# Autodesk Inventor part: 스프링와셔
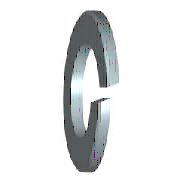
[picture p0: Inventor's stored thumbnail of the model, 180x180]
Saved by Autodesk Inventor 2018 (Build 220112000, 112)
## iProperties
Created: 2012-02
Part Number: 스프링와셔
Material: 강철, 연강
Description: 스프링 와셔
Document SubType Name: Modeling
Standard: JIS B 1251
Designer: mduedu
Standards Organization: JIS
Language: ko-KR
Size Designation: 번호 2 4
Categories: <MemberInstance><Categories><Category DisplayName="조임쇠" InternalName="e4da775c-781d-43d5-af7c-5136215cf5a6" Mnemonic="FSTN"><Category DisplayName="와셔" InternalN
Density: 7.85 g/cm^3
Appearance: 파란색 - 벽 페인트 - 광택
Mass: 0.246957 g
Surface Area: 1.02615 cm^2
Volume: 0.0314594 cm^3
IsCustomPart: 1
Author: mduedu
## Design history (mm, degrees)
sketch "스케치1"
  geometry: C1 r 3.8 at (0, 0); C2 r 2.05 at (0, 0); 1 further point
  constraints: 2 centre point, 2 coincident
  dimensions: "d0" = 4.1 diameter of C2 (= SD1); "d1" = 7.6 diameter of C1 (= SD2)
extrude "본체" new body sketch "스케치1" distance "d2" = 1 (= SD); taper "d3" = 0 deg
sketch "스케치2"
  geometry: L1 (0, -2.05)-(0, 2.05) reference; L2 (1, 3.8)-(1, -3.8) reference; L3 (-1.2, 0)-(7.2, 0) reference; L4 (0, -0.2)-(1, 0.164); L5 (0, 0.2)-(1, 0.564)
  constraints: 4 end point, 4 point on line, 1 parallel
  dimensions: "d4" = 0.2 distance from line of L3 L4.start (= 0.2 x SD); "d5" = 0.2 distance from line of L3 L5.start (= 0.2 x SD); "d6" = 70 deg angle of L2 L4 (= FAWI)
extrude "절단부" cut sketch "스케치2" stored distance "d7" = 1 (= SD); taper "d8" = 0 deg
workaxis "Work Axis1"
workplane "Work Plane1"
body "Solid1"
other parameters: "SD1" = 4.1 [user parameter; used in 1 equation term], "SD2" = 7.6 [user parameter; used in 1 equation term], "SD" = 1 [user parameter; used in 4 equation terms], "FAWI" = 70 deg [user parameter; used in 1 equation term], "d9" = 0, "d10" = 0, "d11" = 0, "d12" = 0, "SDI" = 1.4 [user parameter], "NND" = 4 [user parameter]
